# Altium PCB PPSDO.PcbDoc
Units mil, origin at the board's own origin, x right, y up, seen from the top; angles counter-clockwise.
Board outline 905.51 x 787.4 mil, 4 copper layers (Top Layer, Layer 1, Layer 2, Bottom Layer), stack 28.976 mil thick; 66 components, 56 nets, 228 pads, 101 vias.
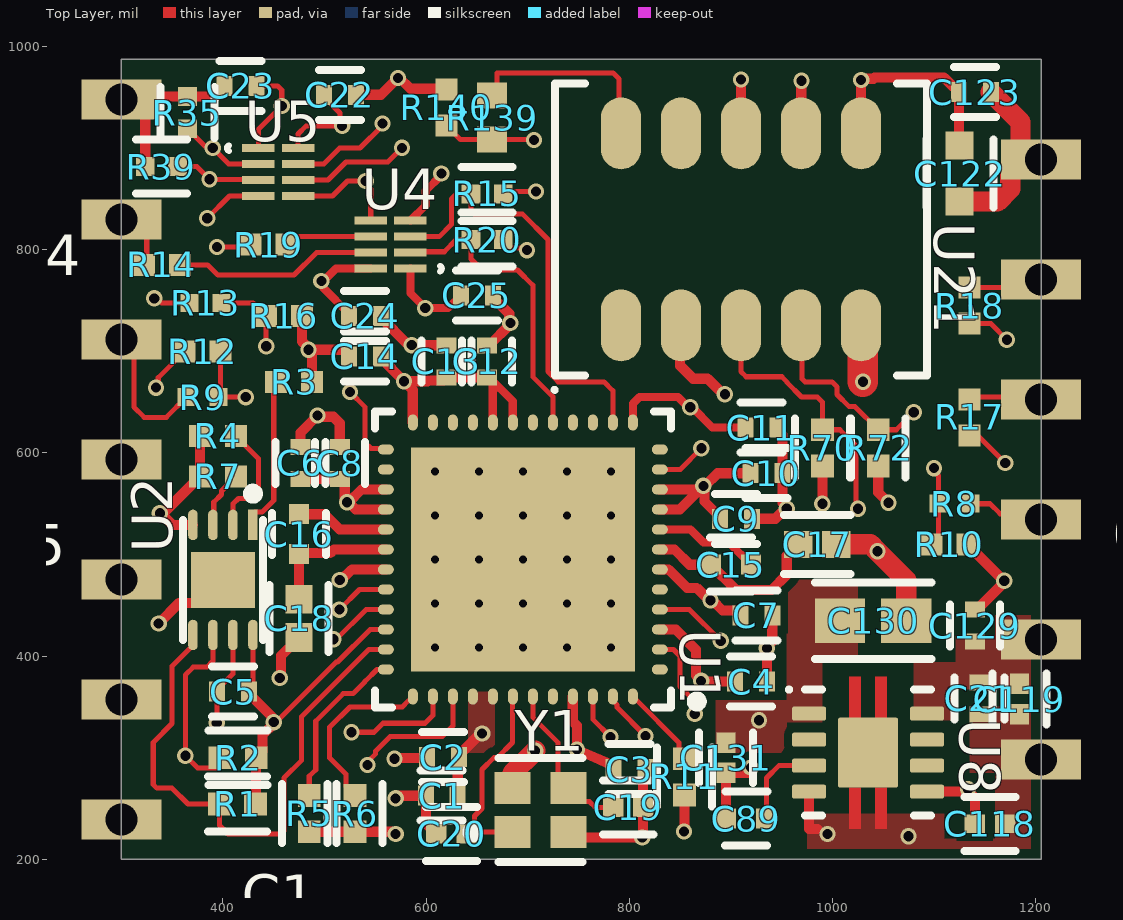
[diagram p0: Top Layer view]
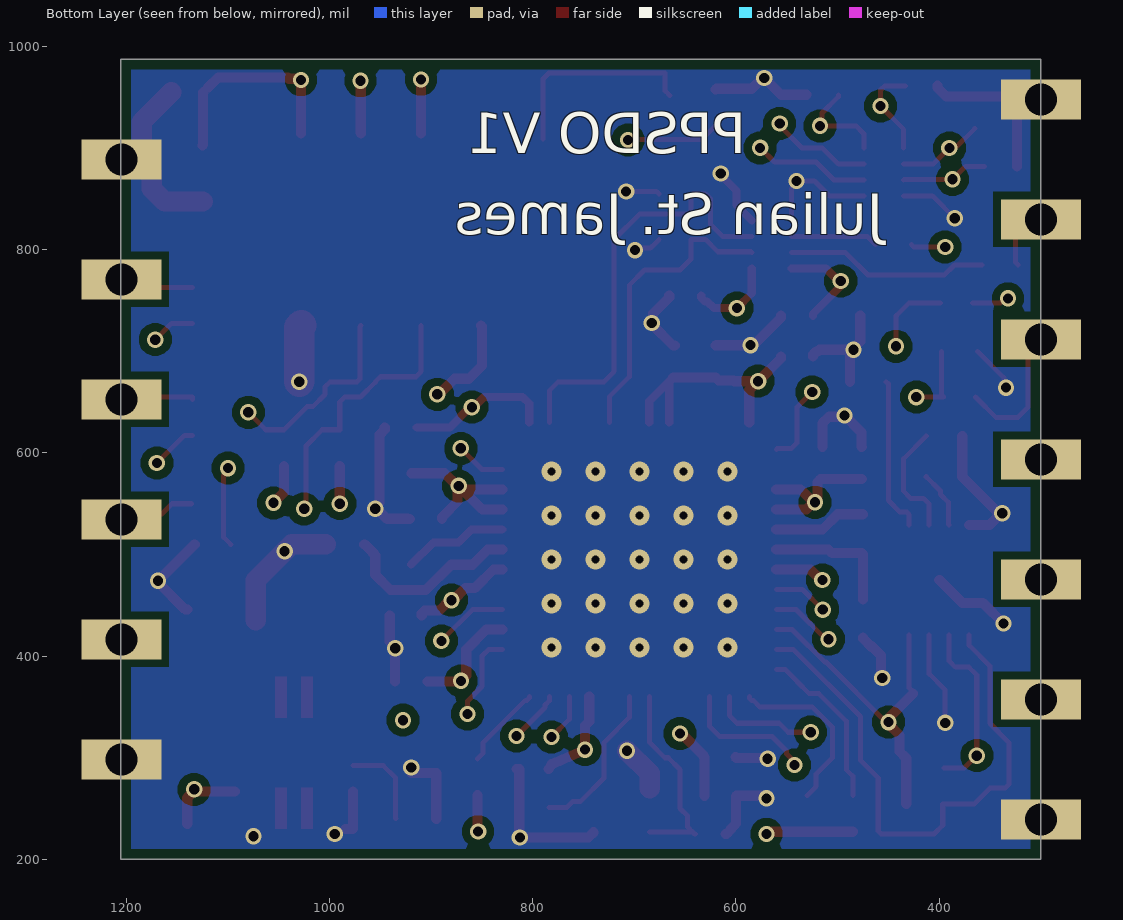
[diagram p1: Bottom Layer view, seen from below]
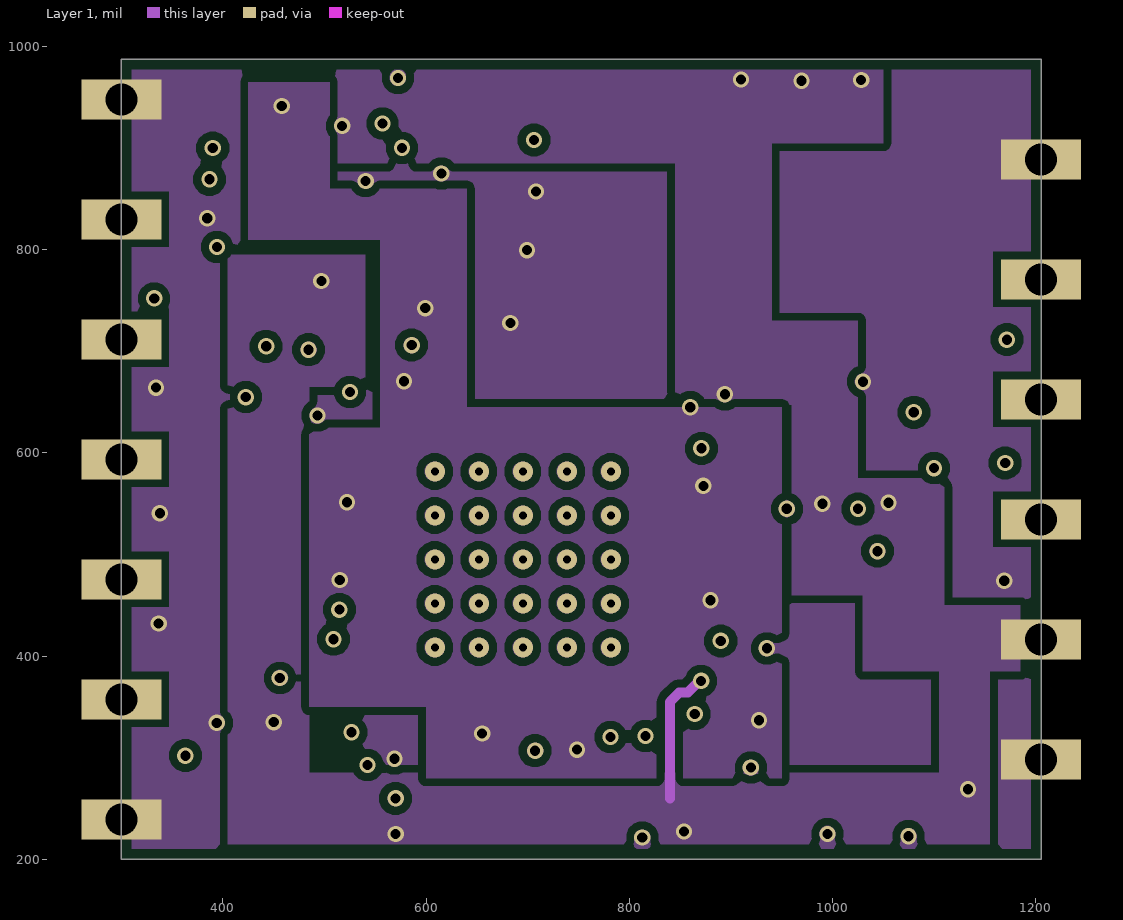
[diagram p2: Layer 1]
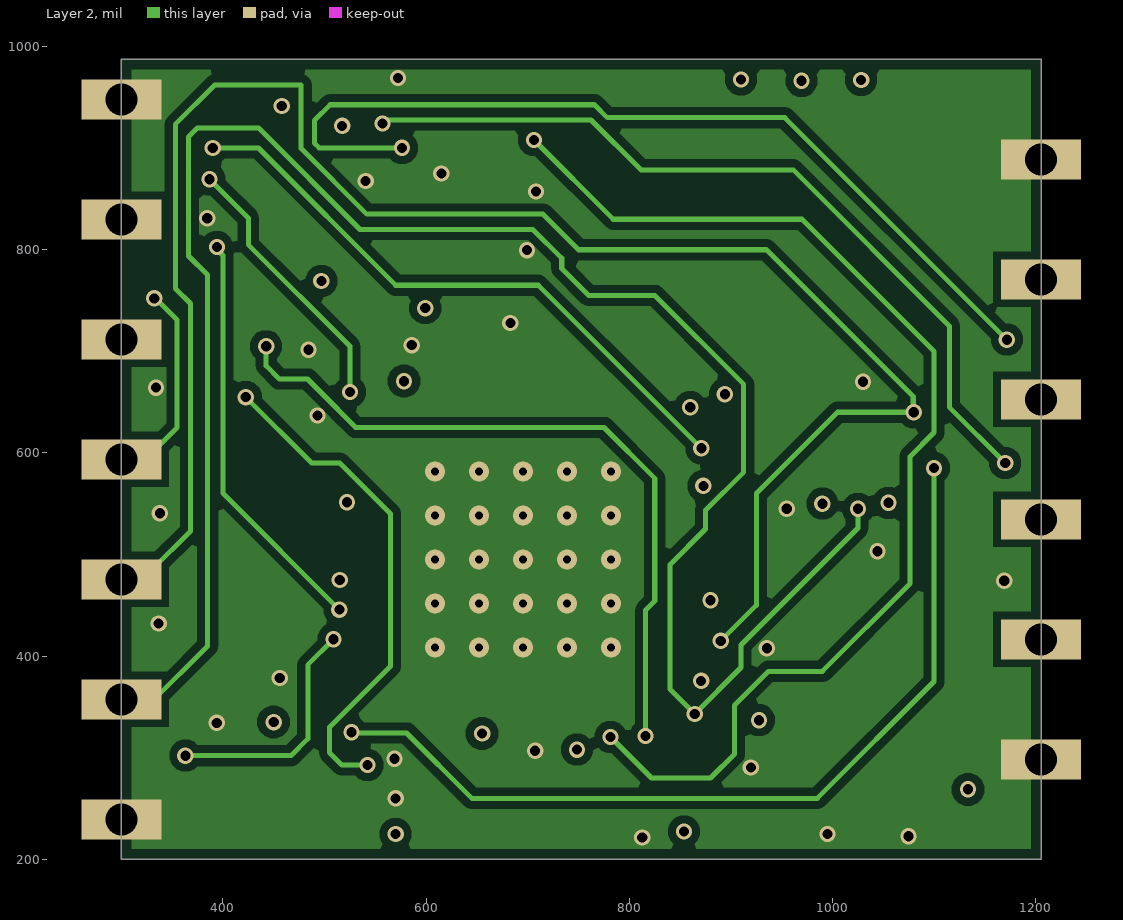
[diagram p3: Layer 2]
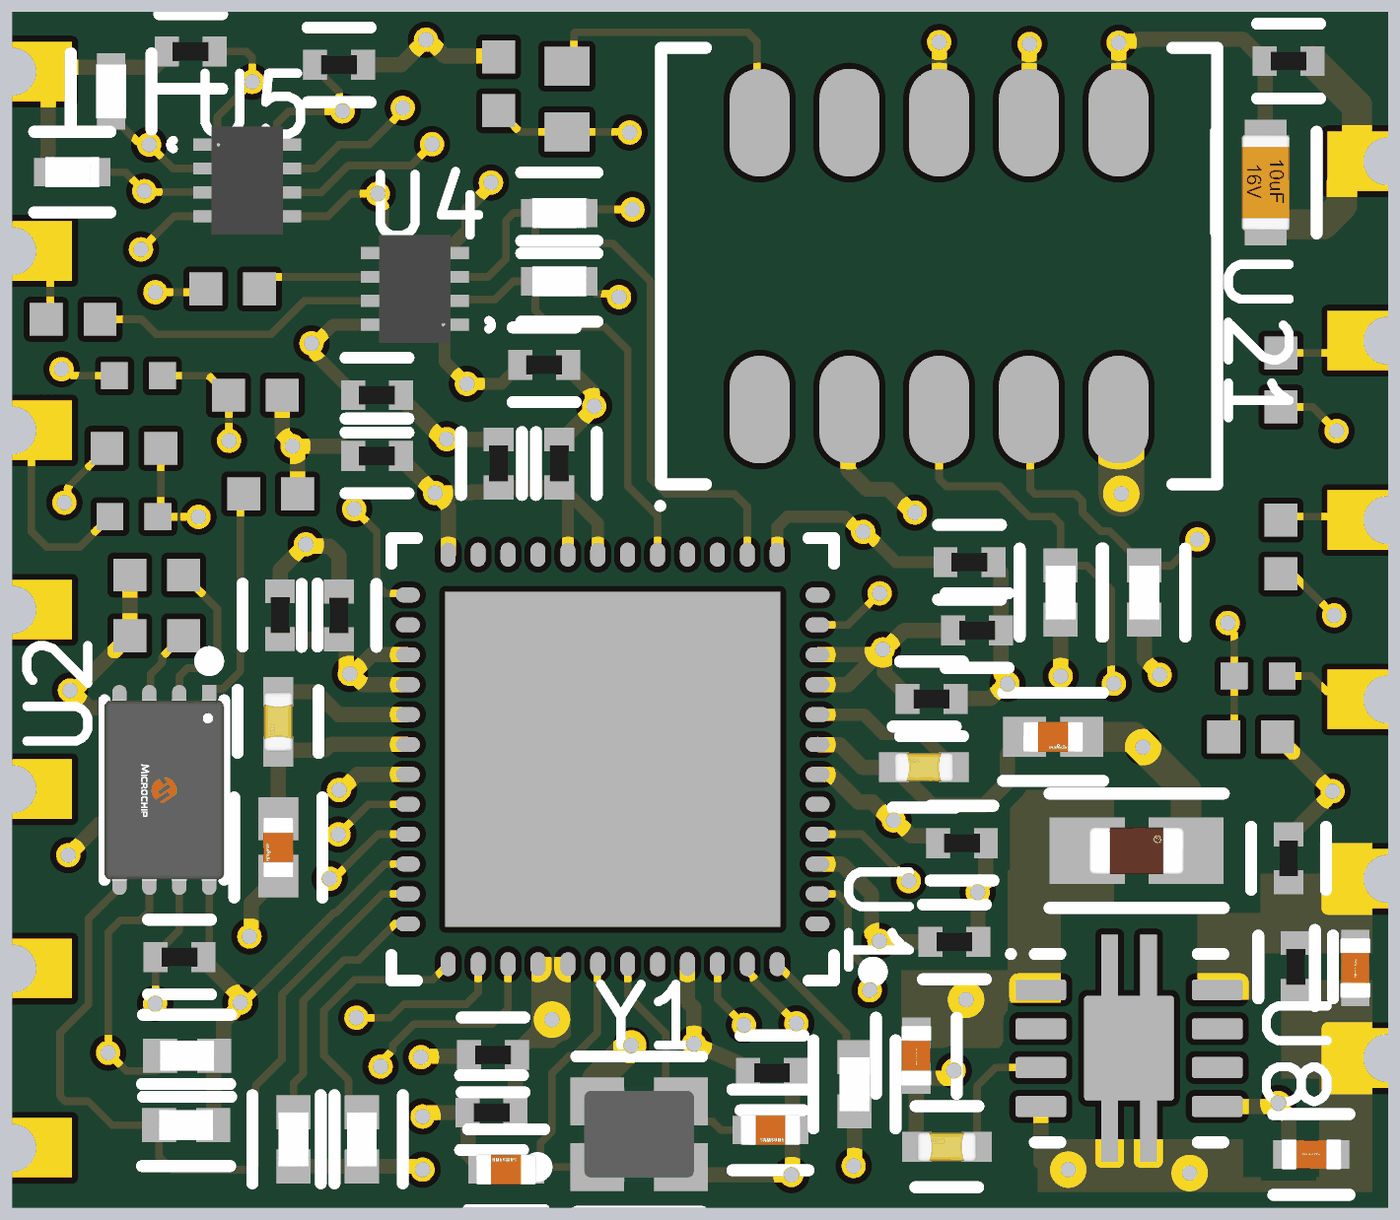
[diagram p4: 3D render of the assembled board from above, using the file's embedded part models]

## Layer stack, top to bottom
Top Solder: solder mask 0.4, Solder Resist, Dk 3.5
Top Layer: signal copper 1.378
Dielectric 2: core 7.9921, Core-009, Dk 4.5
Layer 1: signal copper 1.1811
Dielectric 1: dielectric 7.874, FR-4, Dk 4.8
Layer 2: signal copper 1.1811
Dielectric 3: core 7.9921, Core-009, Dk 4.5
Bottom Layer: signal copper 1.378
Bottom Solder: solder mask 0.4, Solder Resist, Dk 3.5

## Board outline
300,200 300,987.4 1205.51,987.4 1205.51,200

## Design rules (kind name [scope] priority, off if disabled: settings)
BoardOutlineClearance [All] p1: gap=10 ignorepadtopadclearanceinfootprint=FALSE except(0: Arc-SplitContinuation Track-SplitContinuation SMDPad-SplitContinuation THPad-SplitContinuation Via-SplitContinuation Fill-SplitContinuation Poly-SplitContinuation Region-SplitContinuation Text-SplitContinuation)
Clearance [All] p1: gap=8 ignorepadtopadclearanceinfootprint=TRUE
DiffPairsRouting [All] p1: maxlimit=10 minlimit=10 mostfreqgap=10 toplayer_minwidth=15 toplayer_maxwidth=15 toplayer_prefwidth=15 midlayer1_minwidth=15 midlayer1_maxwidth=15 midlayer1_prefwidth=15 midlayer2_minwidth=15 midlayer2_maxwidth=15 midlayer2_prefwidth=15 bottomlayer_minwidth=15 bottomlayer_maxwidth=15 bottomlayer_prefwidth=15 maxuncoupledlength=500
PolygonConnect [All] p1: connectstyle=Direct reliefconductorwidth=10 reliefentries=4 polygonreliefangle="90 Angle" airgapwidth=10
RoutingVias [All] p1: holewidth=10 width=16 viastyle="Through Hole" minholewidth=10 minwidth=16 maxholewidth=28 maxwidth=50
SolderMaskExpansion [All] p1: expansion=4 istentingtop=FALSE
Width [All] p1: maxlimit=50 minlimit=5 preferedwidth=5 minimp=50.000000 maximp=50.000000 favimp=50.000000
29 further rules are at their usual default settings.

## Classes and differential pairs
differential pair class 100ohm: DPLL_9513_1PPS_0 DPLL_9513_1PPS_1 DPLL_OUT_0B DPLL_OUT_1A DPLL_OUT_1B
differential pair DPLL_OUT_1B: +DPLL_OUT_1B_P -DPLL_OUT_1B_N

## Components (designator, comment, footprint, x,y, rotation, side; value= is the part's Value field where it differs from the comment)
C1 "GRM155R71C104KA88D" FP-GRM15-MFG 615.39,262.59 r0 top value=0.10μF
C2 "GRM155R71C104KA88D" FP-GRM15-MFG 616.39,300.57 r0 top value=0.10μF
C3 "GRM155R71C104KA88D" FP-GRM15-MFG 800,288.73 r180 top value=0.10μF
C4 "GRM155R71C104KA88D" FP-GRM15-MFG 920,375 r0 top value=0.10μF
C5 "GRM155R71C104KA88D" FP-GRM15-MFG 410,365 r0 top value=0.10μF
C6 "GRM155R71C104KA88D" FP-GRM15-MFG 476.2,590.19 r270 top value=0.10μF
C7 "GRM155R71C104KA88D" FP-GRM15-MFG 925,440 r0 top value=0.10μF
C8 "GRM155R71C104KA88D" FP-GRM15-MFG 515,590 r270 top value=0.10μF
C9 "GRM155R71C104KA88D" FP-GRM15-MFG 905,535 r0 top value=0.10μF
C10 "GRM155R71C104KA88D" FP-GRM15-MFG 935,580 r0 top value=0.10μF
C11 "GRM155R71C104KA88D" FP-GRM15-MFG 930,625 r0 top value=0.10μF
C12 "GRM155R71C104KA88D" FP-GRM15-MFG 660,690 r270 top value=0.10μF
C13 "GRM155R71C104KA88D" FP-GRM15-MFG 620,690 r270 top value=0.10μF
C14 "GRM155R71C104KA88D" FP-GRM15-MFG 540,695 r0 top value=0.10μF
C15 "CC0402KRX7R9BB392" FP-CC0402-MFG 900,490 r180 top value="3.9 nF"
C16 "CC0402KRX7R9BB392" FP-CC0402-MFG 475,520 r270 top value="3.9 nF"
C17 "GRM155R61A224KE19D" FP-GRM155-0_05-IPC_A 985,510 r0 top
C18 "GRM155R61A224KE19D" FP-GRM155-0_05-IPC_A 475.05,437.17 r270 top
C19 "CL05C6R2CB5NNNC" FP-CL468-IPC_C 798.98,251.15 r0 top
C20 "CL05C6R2CB5NNNC" FP-CL468-IPC_C 625,225 r180 top
C21 "0.1uF_16V_0402" FP-GRM15-MFG 1144.67,358.5 r270 top value=0.10μF
C22 "0.1uF_16V_0402" FP-GRM15-MFG 515,952.48 r0 top value=0.10μF
C23 "0.1uF_16V_0402" FP-GRM15-MFG 417.37,961.32 r180 top value=0.10μF
C24 "0.1uF_16V_0402" FP-GRM15-MFG 540,735 r0 top value=0.10μF
C25 "0.1uF_16V_0402" FP-GRM15-MFG 650,755 r0 top value=0.10μF
C89 "CC0402KRX7R7BB103" FP-CC0402-MFG 915,240 r180 top value="10 nF"
C118 "1uF_16V_0402" FP-0402-L_1_0_0_05-W_0_5-IPC_C 1155,235 r0 top
C119 "1uF_16V_0402" FP-0402-L_1_0_0_05-W_0_5-IPC_C 1183.92,357.78 r270 top
C122 "10uF_16V_0603" FP-C1608-MFG 1125,875 r270 top value=10uF
C123 "GRM155R71C104KA88D" FP-GRM15-MFG 1140,955 r0 top value=0.10μF
C129 "0.1uF_16V_0402" FP-GRM15-MFG 1140,430 r90 top value=0.10μF
C130 "10uF_16V_0603" FP-MK107BA-IPC_A 1040,435 r0 top
C131 "1uF_16V_0402" FP-0402-L_1_0_0_05-W_0_5-IPC_C 895,300 r270 top
R1 "CRCW040210K0JNED" FP-CRCW0402-e3-IPC_B 414.33,254.39 r0 top
R2 "CRCW040210K0JNED" FP-CRCW0402-e3-IPC_B 415,300 r0 top
R3 "49.9_1%_0402" RESC1005X40X25NL05T05 470,670 r180 top
R4 "49.9_1%_0402" RESC1005X40X25NL05T05 395,616.57 r0 top
R5 "CRCW040210K0JNED" FP-CRCW0402-e3-IPC_B 485,245 r270 top
R6 "CRCW040210K0JNED" FP-CRCW0402-e3-IPC_B 530,245 r270 top
R7 "49.9_1%_0402" RESC1005X40X25NL05T05 395,576.57 r0 top
R8 "44.2_1%_0402" RESC1005X40X25LL05T05 1120,550 r0 top
R9 "44.2_1%_0402" RESC1005X40X25LL05T05 380,655 r180 top
R10 "49.9_1%_0402" RESC1005X40X25NL05T05 1115,510 r180 top
R11 "CRCW040210K0JNED" FP-CRCW0402-e3-IPC_B 854.32,281.17 r270 top
R12 "49.9_1%_0402" RESC1005X40X25NL05T05 380,700 r0 top
R13 "44.2_1%_0402" RESC1005X40X25LL05T05 382.94,747.75 r180 top
R14 "49.9_1%_0402" RESC1005X40X25NL05T05 340,785 r0 top
R15 "CRCW0402100RFKED" FP-CRCW0402-e3-IPC_C 660,855 r0 top
R16 "49.9_1%_0402" RESC1005X40X25NL05T05 460,735 r180 top
R17 "49.9_1%_0402" RESC1005X40X25NL05T05 1135,635 r270 top
R18 "49.9_1%_0402" RESC1005X40X25NL05T05 1135,745 r270 top
R19 "49.9_1%_0402" RESC1005X40X25NL05T05 445,805 r0 top
R20 "CRCW0402100RFKED" FP-CRCW0402-e3-IPC_C 660,810 r0 top
R35 "CRCW0402100RFKED" FP-CRCW0402-e3-IPC_C 365,935 r90 top
R39 "CRCW0402100RFKED" FP-CRCW0402-e3-IPC_C 339.41,881.89 r180 top
R70 "CRCW040210K0JNED" FP-CRCW0402-e3-IPC_B 990,605 r270 top
R72 "CRCW040210K0JNED" FP-CRCW0402-e3-IPC_B 1045,605 r270 top
R139 "44.2_1%_0402" RESC0402(1005)_M 665,930 r90 top value="44.20 Ohm"
R140 "49.9_1%_0402" RESC1005X40X25NL05T05 620,940 r270 top
U1 "AD9546" AD9546 695.16,495.16 r180 top
U2 "AT34C02D-MAHM-T" FP-8MA2-IPC_C 400,475 r270 top
U4 "NLSV2T244MUTAG" UDFN8_1P20X1P80_ONS 565,805 r180 top
U5 "NLSV2T244MUTAG" UDFN8_1P20X1P80_ONS 454.5,876.38 r0 top
U8 "TPS73718DRBR" DRB0008A_V 1035,305 r0 top
U21 "SIT5711" SIT5711 910,820 r90 top
Y1 "SXT32410FE16-52.000MT" FP-402-MFG 712.56,248.35 r0 top

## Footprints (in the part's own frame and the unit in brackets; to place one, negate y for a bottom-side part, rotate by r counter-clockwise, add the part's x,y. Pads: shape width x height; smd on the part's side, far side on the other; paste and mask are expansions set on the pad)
AD9546 [mm] "QFN, 48-Leads, Body 7.00x7.00mm, Pitch 0.50mm, Thermal Pad 5.60x5.60mm, IPC Medium Density"
  oval 0.4x0.25 smd: 1(-3.425,2.75) 2(-3.425,2.25) 3(-3.425,1.75) 4(-3.425,1.25) 5(-3.425,0.75) 6(-3.425,0.25) 7(-3.425,-0.25) 8(-3.425,-0.75) 9(-3.425,-1.25) 10(-3.425,-1.75) 11(-3.425,-2.25) 12(-3.425,-2.75) 25(3.425,-2.75) 26(3.425,-2.25) 27(3.425,-1.75) 28(3.425,-1.25) 29(3.425,-0.75) 30(3.425,-0.25) 31(3.425,0.25) 32(3.425,0.75) 33(3.425,1.25) 34(3.425,1.75) 35(3.425,2.25) 36(3.425,2.75)
  oval 0.25x0.4 smd: 13(-2.75,-3.425) 14(-2.25,-3.425) 15(-1.75,-3.425) 16(-1.25,-3.425) 17(-0.75,-3.425) 18(-0.25,-3.425) 19(0.25,-3.425) 20(0.75,-3.425) 21(1.25,-3.425) 22(1.75,-3.425) 23(2.25,-3.425) 24(2.75,-3.425) 37(2.75,3.425) 38(2.25,3.425) 39(1.75,3.425) 40(1.25,3.425) 41(0.75,3.425) 42(0.25,3.425) 43(-0.25,3.425) 44(-0.75,3.425) 45(-1.25,3.425) 46(-1.75,3.425) 47(-2.25,3.425) 48(-2.75,3.425)
  rect 5.6x5.6 smd: 49(0,0)
  silkscreen extent -4.47,-3.7 3.7,3.7, body extent -3.55,-3.55 3.55,3.55, height 0.8
DRB0008A_V [mm] "SON, 8-Leads, Body 3x3mm, Pitch 0.65mm, Thermal Pad 1.50 x 3.8mm"
  rrect29% 0.85x0.35 smd: 1(-1.475,0.975) 2(-1.475,0.325) 3(-1.475,-0.325) 4(-1.475,-0.975) 5(1.475,-0.975) 6(1.475,-0.325) 7(1.475,0.325) 8(1.475,0.975)
  rrect7% 1.5x1.75 smd: 9(0,0)
  Top Layer region: 0.185,0.875 0.185,1.9 0.465,1.9 0.465,0.875
  Top Layer region: -0.185,-0.875 -0.185,-1.9 -0.465,-1.9 -0.465,-0.875
  Top Layer region: 0.185,-0.875 0.185,-1.9 0.465,-1.9 0.465,-0.875
  Top Layer region: -0.185,0.875 -0.185,1.9 -0.465,1.9 -0.465,0.875
  silkscreen extent -2.02,-1.58 1.57,1.62, body extent -1.5,-1.5 1.5,1.5, height 1
FP-8MA2-IPC_C [mm]
  rect 0.761x0.239 smd paste+0 mask+0: 1(-1.376,0.75)
  rrect100% 0.761x0.239 smd paste+0 mask+0: 2(-1.376,0.25) 3(-1.376,-0.25) 4(-1.376,-0.75) 5(1.376,-0.75) 6(1.376,-0.25) 7(1.376,0.25) 8(1.376,0.75)
  rect 1.4x1.6 smd paste-1000 mask+0: 9(0,0)
  silkscreen extent -2.28,-1 1.5,1, body extent -1.86,-1.1 1.86,1.1, height 0.25
FP-0402-L_1_0_0_05-W_0_5-IPC_C [mil]
  rect 20.29x18.6 smd paste+0 mask+0: 1(-14.9,0) 2(14.9,0)
  silkscreen extent -25,-27 25,27, body extent -29,-15 29,15, height 10
FP-402-MFG [mm]
  rect 0.9x0.8 smd paste+0 mask+0: 1(-0.7,-0.55) 2(0.7,-0.55) 3(0.7,0.55) 4(-0.7,0.55)
  silkscreen extent -1.82,-1.3 1.05,1.3, body extent -1.25,-1.05 1.25,1.05, height 0.25
FP-C1608-MFG [mm]
  rect 0.7x0.7 smd paste+0 mask+0: 1(-0.7,0) 2(0.7,0)
  silkscreen extent -0.86,-0.83 0.85,0.85, body extent -1.15,-0.55 1.15,0.55, height 0.25
FP-CC0402-MFG [mm]
  rect 0.5x0.5 smd paste+0 mask+0: 1(-0.5,0) 2(0.5,0)
  silkscreen extent -0.53,-0.68 0.53,0.67, body extent -0.87,-0.48 0.87,0.48, height 0.25
FP-CL468-IPC_C [mil]
  rect 20.29x18.6 smd paste+0 mask+0: 1(-14.9,0) 2(14.9,0)
  silkscreen extent -25,-27 25,27, body extent -29,-15 29,15, height 10
FP-CRCW0402-e3-IPC_B [mil]
  rect 22.37x22.54 smd paste+0 mask+0: 1(-17.8,0) 2(17.8,0)
  silkscreen extent -29,-27 29,27, body extent -35,-17 35,17, height 10
FP-CRCW0402-e3-IPC_C [mil]
  rect 18.43x18.6 smd paste+0 mask+0: 1(-15.83,0) 2(15.83,0)
  silkscreen extent -25,-27 25,27, body extent -29,-15 29,15, height 10
FP-GRM15-MFG [mm]
  rect 0.4x0.5 smd paste+0 mask+0: 1(-0.4,0) 2(0.4,0)
  silkscreen extent -0.53,-0.63 0.53,0.63, body extent -0.7,-0.38 0.7,0.38, height 0.25
FP-GRM155-0_05-IPC_A [mil]
  rect 28.16x26.48 smd paste+0 mask+0: 1(-18.84,0) 2(18.84,0)
  silkscreen extent -33,-29 33,29, body extent -41,-21 41,21, height 10
FP-MK107BA-IPC_A [mil]
  rect 49.52x43.78 smd paste+0 mask+0: 1(-32.57,0) 2(32.57,0)
  silkscreen extent -57,-38 57,38, body extent -77,-42 77,42, height 10
RESC0402(1005)_M [mm] "Chip Resistor, Body 1.0x0.5mm, IPC Low Density"
  rect 0.65x0.75 smd: 1(-0.55,0) 2(0.55,0)
  body extent -0.52,-0.28 0.53,0.28, height 0.4
RESC1005X40X25LL05T05 [mm] "Chip Resistor, 2-Leads, Body 1.00x0.50mm, IPC High Density"
  rect 0.45x0.45 smd: 1(-0.4,0) 2(0.4,0)
  body extent -0.53,-0.27 0.53,0.28, height 0.4
RESC1005X40X25NL05T05 [mm] "Chip Resistor, 2-Leads, Body 1.00x0.50mm, IPC Medium Density"
  rect 0.55x0.55 smd: 1(-0.45,0) 2(0.45,0)
  body extent -0.53,-0.27 0.53,0.28, height 0.4
SIT5711 [mm]
  oval 1.8x1 smd: 1(-2.4,3) 2(-2.4,1.5) 3(-2.4,0) 4(-2.4,-1.5) 5(-2.4,-3) 6(2.4,3) 7(2.4,1.5) 8(2.4,0) 9(2.4,-1.5) 10(2.4,-3)
  silkscreen extent -4.06,-4.65 3.65,4.71, body extent -3.5,-4.5 3.5,4.5, height 6.2
UDFN8_1P20X1P80_ONS [mil]
  rect 32x8 smd paste+0 mask+0: 1(-19.5,23.62) 2(-19.5,7.87) 3(-19.5,-7.87) 4(-19.5,-23.62) 5(19.5,-23.62) 6(19.5,-7.87) 7(19.5,7.87) 8(19.5,23.62)
  silkscreen extent -50,21 -49,26, body extent -24,-36 24,36, height 22

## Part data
C1 C2 C3 C4 C5 C6 C7 C8 C9 C10 C11 C12 C13 C14 C123: library part CMP-2100-03641-2, "CAP CER 0.1UF 16V X7R 0402", Capacitance=0.10μF, Manufacturer=Murata, Package=GRM15, Temperature="-55°C to +125°C", Temperature Characteristic=X7R, Temperature Range High=+125°C, Temperature Range Low=-55°C, Tolerance=10%, Voltage Rating=16Vdc
C15 C16: library part CMP-03422-000890-1, "CAP CER 3900PF 50V X7R 0402", Capacitance="3.9 nF", Manufacturer=YAGEO, Package=CC0402, Temperature="-55°C to +125°C", Temperature Characteristic=X7R, Temperature Coefficient=30ppm/°C, Temperature Range High=+125°C, Temperature Range Low=-55°C, Tolerance=0.1, Voltage Rating="50 V"
C17 C18: library part CMP-2008-04561-5, "CAP CER 0.22UF 10V X5R 0402", Capacitance=220nF, Case Code (Imperial)=0402, Case Code (Metric)=1005, Dielectric=X5R, Dielectric Material=Ceramic, Insulation Resistance=10GR, Max Operating Temperature=85°C, Min Operating Temperature=-55°C, Package Quantity=1, Tolerance=10%, Voltage=10V
C19 C20: library part CMP-13271-000420-1, "Cap Ceramic 6.2pF 50V C0G ±0.25pF SMD 0402 +125°C Paper T/R", Capacitance=6.2pF, Case Code (Imperial)=0402, Case Code (Metric)=1005, Dielectric=C0G, Max Operating Temperature=125°C, Min Operating Temperature=-55°C, Voltage Rating=50V
C21 C22 C23 C24 C25 C129: library part CMP-2100-03641-2, "CAP CER 0.1UF 16V X7R 0402", Capacitance=0.10μF, Manufacturer=Murata, Manufacturer Part Number=GRM155R71C104KA88D, Package=GRM15, Temperature="-55°C to +125°C", Temperature Characteristic=X7R, Temperature Range High=+125°C, Temperature Range Low=-55°C, Tolerance=10%, Voltage Rating=16Vdc
C89: library part CMP-03422-000501-1, "CAP CER 10000PF 16V X7R 0402", Capacitance="10 nF", Manufacturer=YAGEO, Package=CC0402, Temperature="-55°C to +125°C", Temperature Characteristic=X7R, Temperature Coefficient=30ppm/°C, Temperature Range High=+125°C, Temperature Range Low=-55°C, Tolerance=0.1, Voltage Rating="16 V"
C118 C119 C131: library part CMP-14477-003537-2, "None", Capacitance=1uF, Case/Package=0402, Dielectric=X5R, Max Operating Temperature=85°C, Min Operating Temperature=-55°C, Package Quantity=10000, Tolerance=20%, Voltage=16V
C122: library part CMP-08246-000019-1, "CAP CER 10UF 16V X5R 0603", Capacitance=10uF, Manufacturer="TDK Corporation", Manufacturer Part Number=C1608X5R1C106M080AB, Package=C1608, Temperature="-55°C to +85°C", Temperature Characteristic=X5R, Temperature Coefficient=15%, Temperature Range High=+85°C, Temperature Range Low=-55°C, Tolerance=20%, Voltage Rating=16V
C130: library part CMP-2000-06226-3, "None", Capacitance=10uF, Case Code (Imperial)=0603, Case Code (Metric)=1608, Dielectric=X5R, Max Operating Temperature=85°C, Min Operating Temperature=-55°C, Package Quantity=1, Tolerance=20%, Voltage Rating=16V
R1 R2 R5 R6 R11 R70 R72: library part CMP-2002-08136-3, "RES Thick Film, 10kΩ, 5%, 0.063W, 200ppm/°C, 0402", Case Code (Imperial)=0402, Case Code (Metric)=1005, Max Operating Temperature=155°C, Max Power Dissipation=63mW, Min Operating Temperature=-55°C, Package Quantity=1, Resistance=10kR, Temperature Coefficient=200ppm/°C, Tolerance=5%, Voltage Rating=50V
R3 R4 R7 R10 R12 R14 R16 R17 R18 R19 R140: library part CMP-2002-00969-1, Manufacturer=Panasonic, Part Number=ERJ-2RKF49R9X
R8 R9 R13: library part CMP-2002-00011-1, Manufacturer="Vishay Dale", Part Number=CRCW040244R2FKED
R15 R20 R35 R39: library part CMP-1011-00397-3, "RES Thick Film, 100Ω, 1%, 0.063W, 100ppm/°C, 0402", Case Code (Imperial)=0402, Case Code (Metric)=1005, Max Operating Temperature=155°C, Max Power Dissipation=63mW, Min Operating Temperature=-55°C, Package Quantity=10, Resistance=100R, Temperature Coefficient=100ppm/°C, Tolerance=1%, Voltage Rating=50V
R139: library part CMP-1011-00357-1, "44R2 0.063W 1% 0402 (1005 Metric)  SMD", Case-EIA=0402, Case-Metric=1005, Power="0.063 W", Tolerance="1 %"
U2: library part CMP-06313-000130-1, "IC EEPROM 2KBIT I2C 1MHZ 8UDFN"
U4 U5: "No Description Available", Mfr_Name=onsemi
U8: library part CMP-0395-00613-2, "Single Output LDO, 1 A, Fixed 1.8 V Output, 2.2 to 5.5 V Input, with Reverse Current Protection, 8-pin SON (DRB), -40 to 125 degC, Green (RoHS & no Sb/Br)", Manufacturer="Texas Instruments", Rating=Catalog
Y1: library part CMP-06858-000005-1, "CRYSTAL 32.0000MHZ 10PF SMD", Case/Package=SMD/SMT, ESR (Equivalent Series Resistance)=100R, Frequency=52MHz, Frequency Stability=10ppm, Load Capacitance=10pF, Max Operating Temperature=70°C, Min Operating Temperature=-20°C, Package Quantity=3000

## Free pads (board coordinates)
  rect 78.74x39.37 hole 31.5 paste+0 mask+4: 4(300,239.37) 4(300,357.48) 4(300,475.59) 4(300,593.7) 4(300,711.81) 4(300,829.92) 4(300,948.03) 4(1205,298.43) 4(1205,416.54) 4(1205,534.65) 4(1205,652.76) 4(1205,770.87) 4(1205,888.98)

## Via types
v1: diameter 16, hole 10, Top Layer to Bottom Layer, 76 vias
v2: diameter 19.68, hole 7.87, Top Layer to Bottom Layer, 25 vias

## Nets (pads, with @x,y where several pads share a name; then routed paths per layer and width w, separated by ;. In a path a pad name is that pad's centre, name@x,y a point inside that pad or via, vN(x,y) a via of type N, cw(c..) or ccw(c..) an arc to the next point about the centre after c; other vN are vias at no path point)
10M_OUT: pad.4@300,829.92 R14.1 | length 26.1
  Top Layer w5: R14.1 325,787.72 325,810
DPLL_CSB: U1.5
DPLL_LDO0: C15.2 C17.1 U1.7 | length 182.9
  Top Layer w10: U1.7 830.08,504.92 844.46,504.92 859.38,490 C15.2 905.32,465 940,465 955,480 955,498.84 957.08,500.92 957.08,501.76 965.32,510 C17.1
DPLL_LDO1: C16.2 C18.1 U1.30 | length 131.6
  Top Layer w10: C18.1 C16.2 476.02,501.34 505.55,501.34 509.21,505 U1.30
DPLL_LF0: C15.1 U1.8 | length 104.1
  Top Layer w8: U1.8 860.31,524.69 873.16,511.84 897.84,511.84 C15.1
DPLL_LF1: C16.1 U1.29 | length 91.5
  Top Layer w10: C16.1 499.84,539.68 514.84,524.69 U1.29
DPLL_M0: R19.1 U1.32 | length 495
  Top Layer w5: v1(394.11,802.79) 425.07,802.79 R19.1 ; v1(514.62,445.76) 534.49,465.63 U1.32
  Layer 2 w5: v1(394.11,802.79) 394.11,800.25 400,794.36 400,560.38 v1(514.62,445.76)
DPLL_M1: R2.1 U1.33 U2.6 | length 474.4
  Top Layer w5: U2.6 390.16,395.16 384.12,389.12 370.81,389.12 363.01,381.33 v1(363.01,301.99) 375,290 R2.1@395,290 ; v1(508.87,416.62) 511.65,416.62 540.97,445.94 U1.33
  Layer 2 w5: v1(363.01,301.99) 466.99,301.99 483.62,318.62 483.62,391.38 v1(508.87,416.62)
DPLL_M2: R1.1 U1.35 U2.5 | length 555.6
  Top Layer w5: U2.5 370.47,410.57 350,390.1 350,333.58 331.42,315 331.42,273.58 335,270 350,270 365.61,254.39 R1.1 396.53,233.47 405,225 457.07,225 460,227.93 460,280 477.5,297.5 477.5,340.46 543.61,406.57 U1.35
DPLL_M3: R5.1 U1.36 | length 166
  Top Layer w5: R5.1 485,281.77 491.38,288.15 491.38,335.96 518.42,363 528,363 540,375 540,375.27 551.62,386.89 U1.36
DPLL_M4: R6.1 U1.37 | length 173
  Top Layer w5: R6.1 529.92,262.8 521.23,271.49 521.23,283.77 505,300 505,330 525,350 576.57,350 583.01,356.44 584.65,356.44 586.89,358.67 U1.37
DPLL_M5: U1.1
DPLL_OUT_0A_N: U1.12
DPLL_OUT_0A_P: R35.1 U1.11 U5.2 | length 737.2
  Top Layer w5: R35.1 365.08,919.17 382.15,902.1 387.9,902.1 v1(390,900) 405.75,884.25 U5.2 ; U1.11 850.1,583.74 v1(870.89,604.53)
  Layer 2 w5: v1(390,900) 435,900 570,765 710.42,765 v1(870.89,604.53)
DPLL_OUT_0B_N: U1.15
DPLL_OUT_0B_P: R15.1 U1.14 U4.3 | length 429
  Top Layer w5: U4.3 612.87,812.87 625,825 625,850 630,855 R15.1 644.17,837.93 647.1,835 695,835 720,810 720,680 730,670 775,670 783.74,661.26 U1.14
DPLL_OUT_0C_P: R20.1 U1.17 U4.2 | length 298.9
  Top Layer w5: U4.2 585.35,797.98 617.85,797.98 629.87,810 R20.1 644.17,790.83 655,780 690,780 705,765 705,675 724.68,655.32 U1.17
DPLL_OUT_1A_N: U1.26
DPLL_OUT_1A_P: R39.1 U1.25 U5.3 | length 431.1
  Top Layer w5: R39.1 374.27,881.89 v1(386.84,869.32) 387.25,868.91 434.59,868.91 U5.3 ; v1(525,660) 540,645 540,610 545.65,604.35 559.39,604.35 U1.25
  Layer 2 w5: v1(386.84,869.32) 425,831.16 425,805 525,705 v1(525,660)
DPLL_OUT_1B_N: U1.23
DPLL_OUT_1B_P: U1.22
DPLL_REFA: R13.1 R16.2 U1.47 | length 836.4
  Top Layer w5: R13.1 429.54,747.75 R16.2 442.6,734.68 v1(442.6,704.96) ; U1.47 783.74,356.05 788,351.79 788,349.34 v1(816.01,321.34)
  Layer 2 w5: v1(442.6,704.96) 442.6,685.73 455.57,672.76 483.25,672.76 513.34,642.67 513.34,642.38 530.72,625 775,625 825,575 825,454.16 816.01,445.16 v1(816.01,321.34)
DPLL_REFAA: R139.1 R140.2 U1.46 | length 1276.7
  Top Layer w5: R140.2 633.94,908.35 R139.1 705.88,908.35 v1(706.26,907.96) ; U1.46 764.06,337.75 v1(781.51,320.3)
  Layer 2 w5: v1(706.26,907.96) 784.22,830 970,830 1100,700 1100,620 1076.28,596.28 1076.28,471.28 990,385 936.97,385 903.49,351.51 903.49,303.49 880,280 821.81,280 v1(781.51,320.3)
DPLL_REFB: R8.1 R10.2 U1.38 | length 1043.4
  Top Layer w5: v1(526.47,325.06) 548.69,325.06 557.54,333.91 598.91,333.91 606.57,341.57 U1.38 ; R10.2 1104.25,516.97 R8.1 1104.25,577.77 1100,582.02 v1(1100,585)
  Layer 2 w5: v1(526.47,325.06) 527.12,324.42 580.58,324.42 645,260 985,260 1100,375 v1(1100,585)
DPLL_REFBB: R9.1 R12.2 U1.39 | length 697.1
  Top Layer w5: R12.2 397.72,656.97 R9.1 395.86,654.89 v1(422.5,654.89) ; v1(542.35,292.92) 542.35,295.9 550.36,303.9 550.36,306.69 564.58,320.91 615.91,320.91 626.26,331.26 U1.39
  Layer 2 w5: v1(422.5,654.89) 487.4,590 515,590 565,540 565,390 505,330 505,305 517.08,292.92 v1(542.35,292.92)
DPLL_RESETB: R11.1 U1.48 | length 83.4
  Top Layer w5: U1.48 803.43,358.67 805.66,356.44 807.3,356.44 849.01,314.73 849.01,304.28 R11.1
DPLL_SCLK: pad.4@300,357.48 R70.1 U1.2 U21.3 | length 2233.5
  Top Layer w5: U1.2 843.43,406.57 850,400 850,370 864.34,355.66 v1(864.34,343.13) ; U21.3 910,680 915,675 950,675 955,670 955,669.54 969.54,655 985,655 990,650 R70.1 1007.2,622.8 1023.23,606.77 1023.23,546.77 v1(1025,545)
  Layer 2 w5: pad.4@330,355 385,410 385,775 366.14,793.86 366.14,911.14 375,920 435,920 535,820 705.05,820 733.49,791.56 733.49,781.51 760,755 825,755 912.52,667.48 912.52,581.06 875,543.54 875,525 840,490 840,367.47 v1(864.34,343.13) 910,388.8 910,411.01 1025,526.01 v1(1025,545)
DPLL_SDIO: pad.4@300,475.59 R72.1 U1.4 U21.4 | length 1997.8
  Top Layer w5: U1.4 859.06,445.94 v1(890,415) ; U21.4 970,724.57 970,672.93 972.93,670 999.4,670 1004.4,665 1004.4,657.58 1016.47,645.51 1022.21,645.51 1044.92,622.8 R72.1 1062.8,622.8 v1(1080,640)
  Layer 2 w5: pad.4@330,485 368,523 368,747 353.14,761.86 353.14,923.4 391.92,962.18 477,962.18 477,899.62 541.62,835 715,835 750,800 935,800 1079.5,655.5 1079.5,640.5 v1(1080,640) 1005,640 925,560 925,450 v1(890,415)
DPLL_VDD: C1.2 C2.2 C3.2 C6.2 C7.1 C8.2 C9.1 C10.1 C11.1 C12.2 C13.2 C14.2 C23.1 C25.1 C130.1 C131.1 U1.6 U1.9 U1.10 U1.13 U1.19 U1.20 U1.24 U1.27 U1.28 U1.31 U1.40 U1.41 U1.45 U4.1 U5.1 U8.1 | length 1238.8
  Top Layer w5: C23.1 453.68,961.32 457.88,957.12 v1(457.88,941.36) 435,918.48 U5.1
  Top Layer w8: U4.1 584.5,757.12 v1(599.15,742.47) 621.72,742.47 628.41,749.16 630.38,749.16 634.25,753.03 C25.1 ; U1.20 665.63,670.38 661.76,674.25 661.97,674.25 685.32,650.91 U1.19 ; U1.13 803.5,630.08 803.5,648.5 810,655 847.84,655 857.84,645 861.62,645 881.62,625 C11.1
  Top Layer w10: C6.2 476.29,574.35 514.91,574.35 C8.2 516.97,574.25 519.84,571.38 519.84,555.31 522.12,553.04 v1(522.12,551.41) v1@523.74,551.41 ; v1(515,475) 516.62,475 526.94,485.31 U1.31 ; C14.2 555.75,693.03 v1(578.2,670.58) ; U1.28 530.79,544.37 v1@523.74,551.41 ; U1.27 536.39,564.06 v1@523.74,551.41 ; U1.24 586.89,661.89 v1(578.2,670.58) ; C1.2 631.14,300.57 C2.2 632.14,302.54 652.27,322.67 653.99,322.67 v1(655.14,323.82) ; C12.2@661.76,674.25 C12.2 C13.2 617.13,671.38 601.99,671.38 601.2,670.58 v1(578.2,670.58) ; U1.45 744.37,335.6 748.58,331.39 v1(748.58,307.92) 751.46,306.66 781.38,293.57 C3.2 ; U1.6 830.08,485.24 838.69,485.24 856.77,467.16 866.22,467.16 878.38,455 v1(880,455) 881.62,455 891.78,444.84 906.38,444.84 909.25,441.97 C7.1 ; U1.9 849.66,544.37 v1(872.88,567.58) ; U1.10 867.73,564.06 871.25,567.58 v1(872.88,567.58) ; v1@874.5,567.58 886.92,580 C10.1 ; C9.1 889.25,536.97 874.02,552.2 874.02,566.43 v1(872.88,567.58)
  other v1: 927.73,336.91 860,645
DPLL_XOA: C20.1 U1.42 Y1.1 | length 199.1
  Top Layer w5: C20.1 640.75,225 C20.1@642.44,226.69 ; Y1.1 C20.1@642.44,226.69 ; U1.42 685,360 685,315 670,300 666.69,300 655,288.31 655,250 647.55,242.55 647.55,231.8 C20.1@642.44,226.69
DPLL_XOB: C19.1 U1.43 Y1.3 | length 156.6
  Top Layer w5: U1.43 705,339.7 730,314.7 730,280.12 753.37,256.75 760.83,256.75 766.43,251.15 C19.1
GND: C1.1 C2.1 C3.1 C4.2 C5.1 C6.1 C7.2 C8.1 C9.2 C10.2 C11.2 C12.1 C13.1 C14.1 C17.2 C18.2 C19.2 C20.2 C21.2 C22.2 C23.2 C24.2 C25.2 C89.2 C118.2 C119.2 C122.2 C123.2 C129.2 C130.2 C131.2 pad.4@300,239.37 pad.4@300,948.03 pad.4@1205,298.43 pad.4@1205,888.98 R3.1 R4.1 R7.1 R10.1 R12.1 R15.2 R16.1 R20.2 R35.2 R39.2 R140.1 U1.49 U2.4 U2.7 U2.9 U4.4 U4.5 U5.4 U5.5 U8.4 U8.9 U21.5 Y1.2 Y1.4 | length 2272
  Top Layer w5: v1(334.24,664.25) 336.35,666.36 336.35,674.06 R12.1 ; v1(384.64,831.01) 406.39,852.76 U5.4 ; v1(393.97,334.31) 394.25,334.6 C5.1 394.25,366.97 409.84,382.56 U2.7 ; U5.5 507.76,852.76 522.73,867.73 v1(540.5,867.73) 540.5,864.75 545.5,859.74 U4.5 ; R20.2 675.83,809.92 682.55,803.2 682.63,803.2 684.16,801.67 697.21,801.67 v1(699.32,799.57) ; R15.2 678.17,857.34 v1(708.12,857.34)
  Top Layer w8: U4.4 599.68,843.8 599.68,858.05 615,873.38 v1(615,875)
  Top Layer w10: R39.2 pad.4@323.58,933.35 ; pad.4@330.14,952.64 331.95,950.83 R35.2 393.11,950.83 401.62,959.35 C23.2 ; v1(336.77,432.12) 357.09,452.44 377.44,452.44 U2.9 ; U2.4 350.18,529.15 338.79,540.54 v1(337.92,540.54) 339.07,541.69 342.4,541.69 R7.1 R4.1 ; v1(455.99,378.55) 457.14,379.7 457.14,400.43 465.97,409.25 466.81,409.25 475.05,417.49 C18.2 ; C6.1 476.34,606.07 476.34,620 v1(493.09,636.76) 494.24,635.61 508.53,635.61 515,629.14 C8.1 ; R16.1 477.72,709.78 484.33,703.17 v1(484.33,701.55) ; R3.1 487.72,696.53 484.33,699.92 v1(484.33,701.55) ; C14.1 524.25,696.97 521.38,699.84 519.41,699.84 517.71,701.55 v1(484.33,701.55) ; C22.2 555.63,952.48 v1(572.23,969.08) 573.85,969.08 584.55,958.38 619.34,958.38 R140.1 ; C24.2 555.75,733.03 581.57,707.21 584.67,707.21 v1(585.82,706.06) 585.98,705.9 619.84,705.9 C13.1 ; v1(568.86,299.03) 569.63,299.8 599.87,299.8 C2.1 ; v1(570,260) 571.62,260 574.21,262.59 C1.1 600,262.23 600,235.1 604.95,230.14 604.95,229.3 609.25,225 C20.2 ; C12.1 661.97,705.75 682.91,726.69 v1(682.91,727.75) 681.76,728.9 681.76,737.02 665.75,753.03 C25.2 ; Y1.2 745.35,221.46 v1(812.74,221.46) 813.31,222.03 813.31,288.73 C3.1 ; C89.2 895,240 C131.2 920,285.1 920,290 919.87,290 v1(919.61,290.26) ; C9.2 923.38,535 923.62,535.25 943.62,535.25 953.38,545 v1(955,545) ; C4.2 935.57,375.17 935.57,407.49 v1(935.4,407.66) 935.4,409.29 940.75,414.64 C7.2 ; C11.2 945.75,623.03 950.75,618.03 C10.2 950.8,579.94 950.8,550.82 953.85,547.77 v1@953.04,546.96 ; U8.4 976.93,230 985,230 ; R10.1 1168.55,474.17 v1(1168.96,474.17) 1168.96,472.74 1141.97,445.75 C129.2
  Top Layer w20: Y1.4 685,284.56 v1(707.32,306.88) ; C17.2 1037.47,510 v1(1044.22,503.25) 1072.57,474.9 C130.2 ; C122.2 1162.44,847.44 1175,860 pad.4@1175,875 ; C123.2 1185,925.75 1185,910
  Top Layer w30: U21.5 1029.9,723.72 v1(1029.9,670.1)
  other v1: 1074.89,222.76 995,225
  other v2: 608.54,408.54 651.85,408.54 695.16,408.54 738.46,408.54 781.77,408.54 608.54,451.85 651.85,451.85 695.16,451.85 738.46,451.85 781.77,451.85 608.54,495.16 651.85,495.16 695.16,495.16 738.46,495.16 781.77,495.16 608.54,538.46 651.85,538.46 695.16,538.46 738.46,538.46 781.77,538.46 608.54,581.77 651.85,581.77 695.16,581.77 738.46,581.77 781.77,581.77
NetC89_1: C89.1 U8.3 | length 87.1
  Top Layer w5: C89.1 935,240.31 935,280 947.2,292.2 U8.3
NetR3_2: R3.2 U2.1 | length 154.2
  Top Layer w5: U2.1 429.53,539.43 431.74,541.64 438.48,541.64 450,553.16 450,667.72 R3.2
NetR4_2: R4.2 U2.2 | length 114.5
  Top Layer w5: U2.2 410,529.31 410,550 415.25,555.25 427.89,555.25 435,562.35 435,594.29 R4.2
NetR7_2: R7.2 U2.3 | length 56.8
  Top Layer w5: U2.3 391,530 391,551.47 398.61,559.08 398.61,562.47 R7.2
NetR14_2: R14.2 U4.7 | length 201.1
  Top Layer w5: R14.2 385,785 395,775 470,775 492.13,797.13 U4.7
NetR17_2: R17.2 U5.7 | length 948.4
  Top Layer w5: U5.7 499.25,884.25 515,900 535,900 556.98,921.98 v1(556.98,924.14) ; R17.2 1142.72,617.28 v1(1170,590)
  Layer 2 w5: v1(556.98,924.14) 559.96,924.14 563.57,927.76 762.24,927.76 811.4,878.6 961.4,878.6 1115,725 1115,645 v1(1170,590)
NetR18_2: R18.2 U5.6 | length 1052.6
  Top Layer w5: U5.6 503.5,868.5 521.23,886.23 562.21,886.23 v1(576.23,900.25) ; R18.2 1155.73,727.28 v1(1171.58,711.43)
  Layer 2 w5: v1(576.23,900.25) 494.75,900.25 490,905 490,927.07 505.57,942.64 765.74,942.64 778.38,930 953.01,930 v1(1171.58,711.43)
NetR19_2: R19.2 U4.6 | length 86
  Top Layer w5: R19.2 470.59,812.87 U4.6
NetR139_2: R139.2 U21.6 | length 205.6
  Top Layer w5: R139.2 669.69,956.34 669.69,973.59 670,973.9 784.14,973.9 790,968.04 U21.6@790,909.22
NetU1_16: U1.16
NetU1_18: U1.18
NetU1_21: U1.21
NetU1_44: U1.44
NetU8_2: U8.2
NetU8_6: U8.6
NetU8_7: U8.7
NetU21_1: U21.1
NetU21_7: U21.7
P3V3: C4.1 C5.2 C21.1 C22.1 C24.1 C118.1 C119.1 C122.1 C123.1 C129.1 pad.4@1205,416.54 R1.2 R2.2 R5.2 R6.2 R11.2 R70.2 R72.2 U1.3 U1.34 U2.8 U4.8 U5.8 U8.5 U8.8 U21.2 U21.8 U21.9 U21.10 | length 1439.7
  Top Layer w5: C5.2@425.75,363.03 C5.2 429.53,368.78 U2.8 ; v1(450,335) 452.34,335 511.45,394.11 512.76,394.11 544.91,426.26 U1.34 ; U5.8 474,914 481.93,921.93 v1(517.38,921.93) 515.27,924.03 515.27,934.49 499.25,950.51 C22.1
  Top Layer w8: v1@498.42,767.6 498.42,762.8 524.25,736.97 C24.1 ; v1@499.05,769.13 511.3,781.38 U4.8
  Top Layer w10: C5.2@425.75,363.03 v1@447.9,340.88 ; R1.2 432.46,254.72 432.46,299.66 R2.2 438.99,306.18 438.99,322.36 450,333.38 v1(450,335) ; R5.2 R6.2 566.18,227.2 568.38,225 v1(570,225) ; U1.3 830.08,426.18 845.74,426.18 865.5,406.42 865.5,380.86 v1(870.7,375.66) 871.36,375 C4.1@903.43,375 ; U21.2 850,724.57 850,685.86 862.85,673.01 877.1,673.01 892.39,657.72 v1(894.02,657.72) ; v1(853.77,227.42) 854.32,227.42 R11.2 ; U21.8 v1(910.02,967.54) ; U21.9 969.29,914.72 969.29,966.05 v1(969.52,966.28) ; v1(990,550) R70.2 ; U21.10 1028.17,914.55 v1(1028.17,967.11) 1029.32,968.26 1040.04,968.26 1041.17,969.39 1109.86,969.39 C123.1@1119.41,959.84 ; R72.2 1045,561.01 v1(1055.14,550.87) ; U8.5 v1@1129.36,266.61 ; C123.1 1124.63,954.63 1124.63,902.93 C122.1 ; v1(1133.26,268.89) 1133.26,267.26 1140.1,260.43 C118.1
  Layer 1 w10: 840,260 840,355 849.13,364.13 857.55,364.13 869.08,375.66 v1(870.7,375.66)
  other v1: 496.89,769.13
PPS_DISC_IN: pad.4@1205,534.65 R8.2 | length 33.4
  Top Layer w5: R8.2 1155,550 1165,540
PPS_MEAS_IN0: pad.4@300,711.81 R9.2 | length 114.2
  Top Layer w5: pad.4@312.5,695 312.5,645 322.5,635 344.25,635 R9.2
PPS_MEAS_IN1: pad.4@300,593.7 R13.2 | length 212.7
  Top Layer w5: v1(332.38,752.12) 335.36,752.12 339.73,747.75 R13.2
  Layer 2 w5: pad.4@327.5,597.5 355,625 355,730.72 333.59,752.12 v1(332.38,752.12)
PPS_OUT_0: pad.4@1205,652.76 R17.1 | length 32.3
  Top Layer w5: R17.1 1135,655 1165,655
PPS_OUT_1: pad.4@1205,770.87 R18.1 | length 40.3
  Top Layer w5: R18.1 1173.45,762.72 pad.4@1174.73,764

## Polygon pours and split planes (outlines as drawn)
DPLL_VDD on Top Layer "NONET_L-01_P-001" (solid, remove dead copper, pour order 4): 990,395 1025,395 1025,475 955,475 955,356.44 885,356.44 885,305 955,305 955,335 990,335
GND on Top Layer "NONET_L-01_P-001" (solid, remove dead copper, pour order 3): 1135,350 1135,285 1160,285 1160,220 1110,220 1110,245 975,245 975,200 1205,200 1205,350
P3V3 on Top Layer "NONET_L-01_P-001" (solid, remove dead copper, pour order 2): 1083.41,336.91 1120,336.91 1120,367.44 1197.84,367.44 1197.84,440 1160,440 1160,420 1121.37,420 1121.37,393.85 1080,393.85 1080,337.46 1103.77,337.46
DPLL_VDD on Top Layer "NONET_L-01_P-001" (solid, remove dead copper, pour order 0): 641.7,365 641.7,305 667.43,305 667.43,365
GND on Bottom Layer "NONET_L-01_P-001" (solid, remove dead copper, pour order 1): 300,985 1205,985 1205,200 300,200
GND on Layer 1 "NONET_L-01_P-001" (solid, remove dead copper, pour order 8): 300,985 1205,985 1205,200 300,200
P3V3 on Layer 1 "NONET_L-01_P-001" (solid, remove dead copper, pour order 7): 1155,395 1105,395 1105,285 1015,285 485,285 485,665 540,665 540,795 405,795 405,215 1155,215
P3V3 on Layer 1 "NONET_L-01_P-001" (solid, remove dead copper, pour order 6): 1185,385 1185,450 1110,450 1110,575 1025,575 1025,730 940,730 940,905 1050,905 1050,985 505,985 505,885 845,885 845,647.27 960,647.27 960,460 1030,460 1030,385 1095,385
DPLL_VDD on Layer 1 "NONET_L-01_P-001" (solid, remove dead copper, pour order 5): 950,645 950,280 600,280 600,350 485,350 485,625 555,625 555,810 425,810 425,965 505,965 505,860 640,860 640,645
GND on Layer 2 "NONET_L-01_P-001" (solid, remove dead copper, pour order 9): 300,985 1205,985 1205,200 300,200 300,260

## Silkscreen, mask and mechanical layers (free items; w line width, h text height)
Bottom Overlay:
  text "PPSDO V1" at 590,895 h40
  text "Julian St. James" at 455,815 h40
